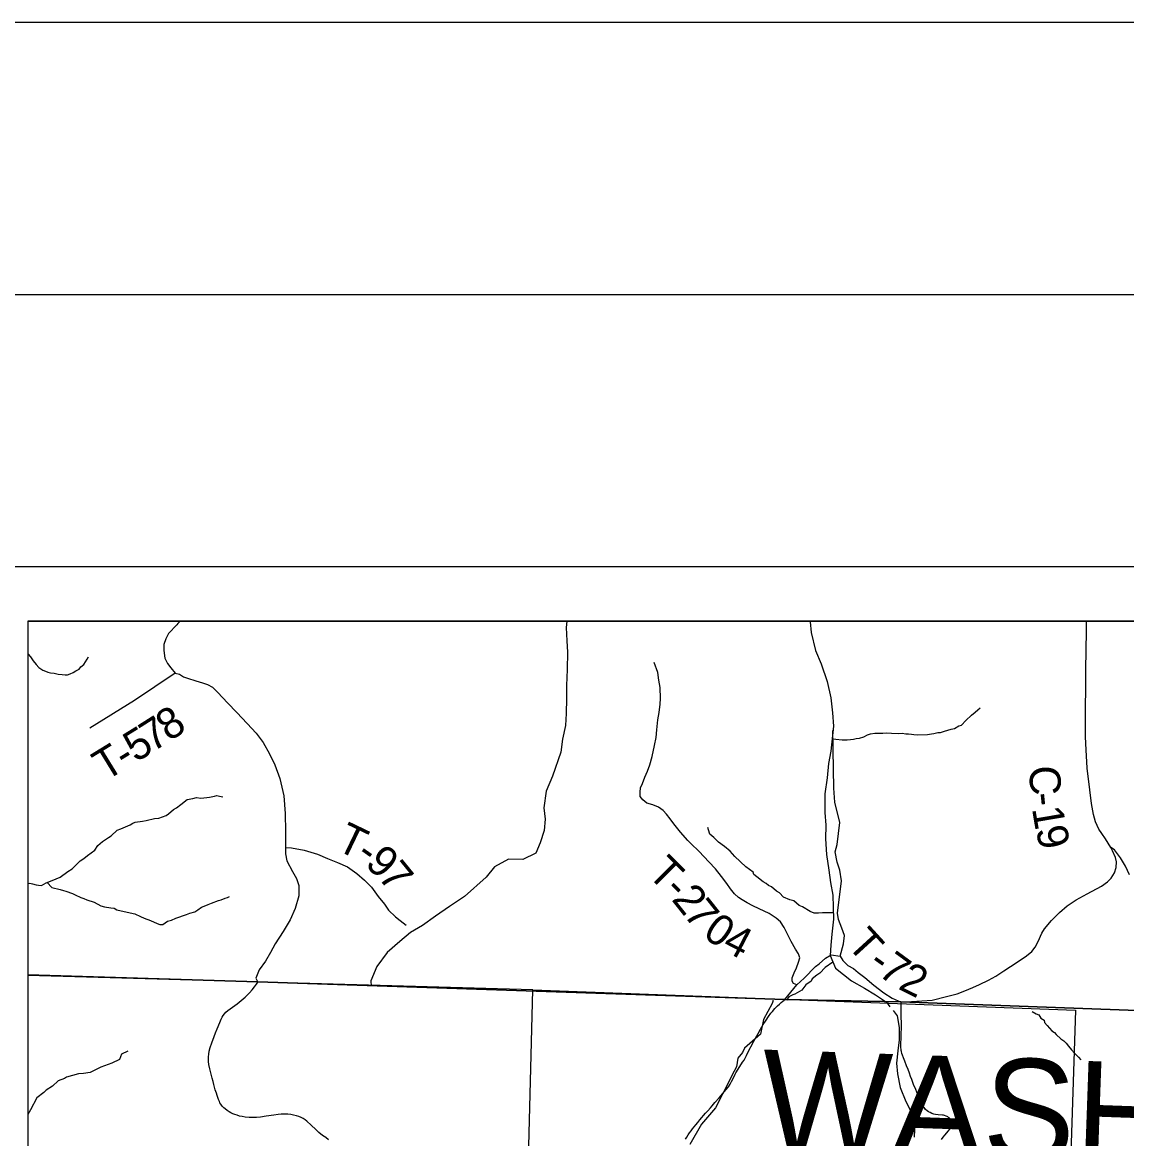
# Model space of a CAD drawing. Extents: x 6.3 to 40.3, y 9 to 31.
# Drawn here: x 8.435 to 10.464, y 28.995 to 31.046 of the extents above; entities that cross this region are included whole.
import ezdxf

# ---------------------------------------------------------------- set-up
doc = ezdxf.new("R2010")
doc.units = 0
for name, color, linetype in [('Default', 7, 'Continuous'), ('GM_X_Corporation', 7, 'Continuous'), ('GM_X_County_Road', 7, 'Continuous'), ('GM_X_County_Road_Text', 7, 'Continuous'), ('GM_X_County_Text', 7, 'Continuous'), ('GM_X_Minor_River', 7, 'Continuous'), ('GM_X_Section', 7, 'Continuous'), ('GM_X_Township_Road', 7, 'Continuous'), ('GM_X_Township_Road_Text', 7, 'Continuous'), ('SH_Border', 7, 'Continuous'), ('SH_Cut_Line', 7, 'Continuous'), ('SH_Data', 7, 'Continuous')]:
    doc.layers.add(name, color=color, linetype=linetype)

msp = doc.modelspace()

# ---------------------------------------------------------------- linework, layer by layer
at = {"layer": 'Default'}
for points in [[(13.1323, 29.9457), (8.4446, 29.9457), (8.4446, 27.9161), (8.9627, 27.9002), (9.9314, 27.8681), (10.145, 27.8635), (10.7129, 27.8423), (11.7175, 27.8106), (12.5872, 27.7766), (13.0625, 27.76), (13.0974, 28.6191), (13.1136, 29.1637), (13.1156, 29.231), (13.116, 29.2473), (13.13, 29.8856)], [(12.9998, 29.9457), (8.4446, 29.9457), (8.4446, 29.2958), (8.8673, 29.2829), (9.8361, 29.2507), (10.0496, 29.2462), (10.6176, 29.225), (11.6221, 29.1933), (12.4918, 29.1593), (12.9672, 29.1426)]]:
    msp.add_lwpolyline(points, close=True, dxfattribs=at)
msp.add_lwpolyline([(12.9672, 29.1426), (12.4918, 29.1593), (11.6221, 29.1933), (10.6176, 29.225), (10.0496, 29.2462), (9.8361, 29.2507), (8.8673, 29.2829), (8.4446, 29.2958), (8.4446, 23.1457)], dxfattribs=at)
at = {"layer": 'GM_X_Corporation'}
msp.add_lwpolyline([(8.4446, 29.2945), (8.4446, 28.2864), (9.3471, 28.2622), (9.3732, 29.268)], close=True, dxfattribs=at)
at = {"layer": 'GM_X_County_Road'}
for points in [[(10.4353, 29.5296), (10.4256, 29.5455), (10.4186, 29.5552), (10.4134, 29.5635), (10.4074, 29.5766), (10.4033, 29.5901), (10.3997, 29.6106), (10.3965, 29.6359), (10.392, 29.6757), (10.3897, 29.7091), (10.3888, 29.7332), (10.3888, 29.7526), (10.3891, 29.856), (10.3906, 29.9279), (10.3908, 29.9457)], [(10.0498, 29.2457), (10.1069, 29.2492), (10.1335, 29.2558), (10.1526, 29.2608), (10.1667, 29.2666), (10.1816, 29.2724), (10.194, 29.2782), (10.2106, 29.2857), (10.2239, 29.2932), (10.2389, 29.3031), (10.2629, 29.3189), (10.2804, 29.3305), (10.2903, 29.3388), (10.2961, 29.3463), (10.3019, 29.3571), (10.3086, 29.372), (10.3135, 29.3803), (10.326, 29.3953), (10.3409, 29.4102), (10.3553, 29.4227), (10.3713, 29.4333), (10.3915, 29.4448), (10.4181, 29.4588), (10.4294, 29.4664), (10.4362, 29.4736), (10.4418, 29.4829), (10.4452, 29.493), (10.4456, 29.5031), (10.4436, 29.5115), (10.4386, 29.5236), (10.4353, 29.5296)], [(10.124, 28.9929), (10.127, 28.9975), (10.1301, 29.0013), (10.1338, 29.0054), (10.1364, 29.0082), (10.1396, 29.012), (10.1405, 29.0132), (10.1412, 29.0143), (10.1417, 29.0154), (10.1421, 29.0164), (10.1424, 29.0177), (10.1425, 29.0189), (10.1427, 29.0206), (10.1426, 29.0227), (10.1425, 29.0241), (10.1423, 29.0254), (10.1419, 29.0269), (10.1413, 29.0285), (10.1407, 29.0298), (10.1397, 29.0312), (10.1387, 29.0325), (10.1379, 29.0332), (10.137, 29.0339), (10.1358, 29.0347), (10.1344, 29.0355), (10.1327, 29.0363), (10.1297, 29.0374), (10.1278, 29.0379), (10.1259, 29.0381), (10.1178, 29.0388), (10.113, 29.0393), (10.1097, 29.0399), (10.1062, 29.041), (10.103, 29.0425), (10.1004, 29.044), (10.0975, 29.0461), (10.0948, 29.0486), (10.092, 29.0518), (10.0907, 29.0535), (10.0896, 29.0552), (10.0874, 29.0589), (10.0843, 29.0656), (10.0785, 29.0802), (10.0766, 29.0852), (10.0729, 29.0944), (10.0696, 29.1033), (10.0674, 29.1088), (10.065, 29.1152), (10.0626, 29.1215), (10.0597, 29.1288), (10.0565, 29.137), (10.0541, 29.1434), (10.0523, 29.148), (10.0513, 29.1513), (10.0504, 29.1547), (10.05, 29.1567), (10.0498, 29.1585), (10.0494, 29.1621), (10.0494, 29.1654), (10.0493, 29.1696), (10.0498, 29.1794), (10.0502, 29.1881), (10.0504, 29.1975), (10.0505, 29.2057), (10.0502, 29.2198), (10.0501, 29.2277), (10.0501, 29.2305)], [(10.0501, 29.2305), (10.05, 29.2353), (10.0498, 29.2457)]]:
    msp.add_lwpolyline(points, dxfattribs=at)
at = {"layer": 'GM_X_Minor_River'}
for points in [[(9.4355, 29.9457), (9.434, 29.9337), (9.4352, 29.9092), (9.4367, 29.8888), (9.4359, 29.8567), (9.4348, 29.8273), (9.4348, 29.8035), (9.434, 29.7759), (9.4329, 29.7541), (9.4272, 29.7288), (9.4242, 29.7046), (9.4094, 29.6608), (9.3977, 29.6333), (9.3931, 29.6023), (9.3954, 29.5819), (9.3939, 29.5608), (9.3867, 29.5385), (9.3784, 29.5193), (9.3549, 29.5076), (9.328, 29.5083), (9.3026, 29.4944), (9.2875, 29.4751), (9.2474, 29.4396), (9.2201, 29.4215), (9.194, 29.4034), (9.1705, 29.3864), (9.1482, 29.3736), (9.1285, 29.3569), (9.105, 29.3369), (9.0861, 29.3113), (9.0755, 29.2845), (9.0758, 29.2747)], [(9.8823, 29.9457), (9.8826, 29.9443), (9.8845, 29.9247), (9.8928, 29.8914), (9.9027, 29.8669), (9.914, 29.8344), (9.9208, 29.8046)], [(8.4446, 29.8861), (8.4457, 29.8847), (8.4496, 29.8802), (8.4547, 29.8724), (8.4602, 29.8656), (8.4648, 29.8604), (8.4725, 29.8553), (8.4771, 29.8535), (8.4817, 29.8521), (8.4867, 29.8507), (8.4931, 29.8497), (8.5004, 29.8483), (8.508, 29.8473), (8.5137, 29.8471), (8.5179, 29.8472), (8.5224, 29.8488), (8.528, 29.8512), (8.5333, 29.8544), (8.5389, 29.8572), (8.5422, 29.8614), (8.5478, 29.8661), (8.5511, 29.8707), (8.5537, 29.8757), (8.5562, 29.88)], [(9.9208, 29.8046), (9.9239, 29.7771), (9.9258, 29.7525), (9.9205, 29.7065), (9.9163, 29.6838), (9.914, 29.6574), (9.9095, 29.628), (9.9095, 29.594), (9.9114, 29.571), (9.911, 29.5457), (9.9129, 29.517), (9.9167, 29.4879), (9.9201, 29.4656), (9.9242, 29.4422), (9.9257, 29.3977), (9.9227, 29.3705), (9.9204, 29.3505), (9.9193, 29.3312), (9.9291, 29.3082), (9.9586, 29.2848), (9.9825, 29.2712), (10.0026, 29.2588), (10.023, 29.2452), (10.0293, 29.2371)], [(9.9231, 29.7293), (9.9254, 29.7291), (9.9296, 29.7284), (9.9417, 29.7272), (9.9505, 29.7274), (9.9569, 29.7279), (9.9622, 29.7284), (9.9675, 29.7297), (9.9732, 29.7306), (9.9814, 29.733), (9.9878, 29.7366), (9.9935, 29.7382), (10.0018, 29.7396), (10.0162, 29.7399), (10.0223, 29.7404), (10.0321, 29.7399), (10.0454, 29.739), (10.0515, 29.7395), (10.0587, 29.7386), (10.0633, 29.7383), (10.069, 29.7376), (10.0732, 29.737), (10.0804, 29.7368), (10.0982, 29.7372), (10.1054, 29.7388), (10.11, 29.7393), (10.1171, 29.741), (10.1224, 29.7411), (10.1296, 29.7432), (10.142, 29.7469), (10.1477, 29.7485), (10.156, 29.7529), (10.1609, 29.7545), (10.1686, 29.7631), (10.179, 29.7728), (10.1861, 29.7783), (10.1906, 29.7825), (10.1954, 29.7865)], [(8.4446, 29.4634), (8.4485, 29.4642), (8.4535, 29.4631), (8.4603, 29.461), (8.4645, 29.4604), (8.4702, 29.4601), (8.4785, 29.4648), (8.4837, 29.4665), (8.4969, 29.4721), (8.504, 29.4753), (8.5186, 29.4855), (8.5261, 29.4902), (8.541, 29.5054), (8.5477, 29.5093), (8.5544, 29.5148), (8.5678, 29.525), (8.5737, 29.5331), (8.5823, 29.5405), (8.5928, 29.5483), (8.598, 29.5511), (8.6092, 29.5616), (8.6156, 29.5641), (8.6332, 29.5713), (8.6377, 29.5744), (8.6422, 29.5761), (8.6555, 29.5779), (8.6623, 29.5792), (8.6778, 29.5829), (8.6853, 29.5835), (8.6989, 29.5887), (8.7034, 29.5915), (8.7127, 29.5997), (8.7179, 29.6025), (8.7262, 29.6087), (8.7377, 29.6177), (8.7479, 29.6198), (8.7551, 29.6215), (8.7627, 29.6206), (8.7741, 29.6216), (8.7786, 29.6221), (8.788, 29.6242), (8.7922, 29.625), (8.7972, 29.624), (8.8033, 29.623)], [(9.9253, 29.4096), (9.9153, 29.4097), (9.9054, 29.4099), (9.8979, 29.4089), (9.8903, 29.4088), (9.883, 29.412), (9.8688, 29.4208), (9.8626, 29.4234), (9.8526, 29.4315), (9.8453, 29.4336), (9.8338, 29.4383), (9.8261, 29.4465), (9.8211, 29.4494), (9.8114, 29.4572), (9.8064, 29.4597), (9.8018, 29.4638), (9.7964, 29.4667), (9.7848, 29.4756), (9.7794, 29.48), (9.7778, 29.4845), (9.7643, 29.4941), (9.7445, 29.513), (9.7356, 29.5227), (9.7252, 29.5316), (9.714, 29.5397), (9.7054, 29.5483), (9.6985, 29.5542), (9.6957, 29.5621), (9.6944, 29.5662)], [(8.4804, 29.4654), (8.4889, 29.4563), (8.5042, 29.4525), (8.5103, 29.4507), (8.5145, 29.4497), (8.5267, 29.445), (8.5317, 29.4429), (8.5421, 29.4378), (8.5478, 29.436), (8.5532, 29.4335), (8.5669, 29.4292), (8.5792, 29.4227), (8.5857, 29.4209), (8.5971, 29.4189), (8.6036, 29.4179), (8.6086, 29.4153), (8.633, 29.4094), (8.6414, 29.4077), (8.6521, 29.403), (8.6586, 29.3997), (8.6705, 29.3958), (8.6824, 29.39), (8.6877, 29.3882), (8.6927, 29.3883), (8.7016, 29.3943), (8.7088, 29.3963), (8.7167, 29.3999), (8.7363, 29.4064), (8.7427, 29.4089), (8.7517, 29.4117), (8.7574, 29.4149), (8.7641, 29.42), (8.769, 29.4216), (8.7761, 29.4248), (8.7821, 29.4272), (8.7953, 29.4325), (8.8002, 29.4337), (8.8074, 29.4365), (8.8115, 29.4378), (8.8156, 29.4394)], [(9.9244, 29.3192), (9.9103, 29.3093), (9.9003, 29.2988), (9.895, 29.2953), (9.8861, 29.2882), (9.8843, 29.284), (9.8749, 29.2773), (9.8676, 29.2677), (9.8548, 29.2602), (9.8507, 29.2589), (9.8436, 29.2553), (9.8391, 29.2492)], [(9.8148, 29.247), (9.8149, 29.2488), (9.8131, 29.243), (9.7967, 29.2136), (9.7913, 29.187), (9.7623, 29.1612), (9.7586, 29.1532), (9.75, 29.1428), (9.7475, 29.1265), (9.7396, 29.1123), (9.7341, 29.1001), (9.7088, 29.0512), (9.6829, 29.0213), (9.6616, 28.9839)], [(10.035, 29.2299), (10.0423, 29.2206), (10.0461, 29.1987), (10.0465, 29.1764), (10.0438, 29.1561), (10.0415, 29.1334), (10.0434, 29.1141), (10.0483, 29.0885), (10.0586, 29.0632), (10.0714, 29.0379), (10.0744, 29.0118), (10.0737, 28.9975)], [(10.291, 29.2285), (10.2982, 29.2239), (10.3027, 29.222), (10.3066, 29.2164), (10.3127, 29.2122), (10.3135, 29.2081), (10.3185, 29.2028), (10.327, 29.193), (10.3316, 29.19), (10.335, 29.1859), (10.3431, 29.1784), (10.3492, 29.1743), (10.3534, 29.1701), (10.3576, 29.1645), (10.363, 29.1581), (10.3688, 29.1517), (10.3757, 29.1442), (10.3799, 29.1396)], [(8.6289, 29.1556), (8.6168, 29.1498), (8.6135, 29.1402), (8.5995, 29.1336), (8.5791, 29.1262), (8.5681, 29.1204), (8.5594, 29.1165), (8.5469, 29.1145), (8.5382, 29.1136), (8.5268, 29.1105), (8.5162, 29.1077), (8.5121, 29.1054), (8.5004, 29.1007), (8.4902, 29.0914), (8.4785, 29.0841), (8.474, 29.0795), (8.4612, 29.0695), (8.45, 29.0477), (8.4446, 29.0394)]]:
    msp.add_lwpolyline(points, dxfattribs=at)
at = {"layer": 'GM_X_Section'}
msp.add_lwpolyline([(9.3732, 29.268), (10.3703, 29.2306), (10.3378, 28.2352), (9.3471, 28.2622)], close=True, dxfattribs=at)
at = {"layer": 'GM_X_Township_Road'}
msp.add_line((8.7251, 29.9457), (8.7207, 29.9411), dxfattribs=at)
for points in [[(8.7207, 29.9411), (8.7185, 29.9388), (8.7036, 29.923), (8.6986, 29.913), (8.6946, 29.9029), (8.6946, 29.8919), (8.6966, 29.8778), (8.7016, 29.8678), (8.7076, 29.8598), (8.7156, 29.8497), (8.7234, 29.8482), (8.7308, 29.843), (8.7381, 29.8408), (8.7539, 29.8356), (8.7656, 29.8324), (8.775, 29.8293), (8.7845, 29.824), (8.794, 29.8145), (8.812, 29.7955), (8.8289, 29.7775), (8.8478, 29.7575), (8.8647, 29.7396), (8.8774, 29.7227), (8.889, 29.7016), (8.8985, 29.6816), (8.908, 29.6562), (8.9153, 29.6246), (8.9175, 29.5919), (8.9185, 29.5592), (8.9185, 29.5296), (8.9185, 29.518), (8.9206, 29.5054), (8.9312, 29.4853), (8.9386, 29.4727), (8.9428, 29.46), (8.9428, 29.441), (8.9364, 29.4178), (8.9269, 29.3967), (8.9143, 29.3756), (8.8995, 29.3524), (8.8911, 29.3366), (8.8816, 29.3207), (8.87, 29.3049), (8.8638, 29.2898), (8.8675, 29.2823)], [(9.6745, 29.5265), (9.6675, 29.5325), (9.658, 29.5426), (9.6443, 29.5581), (9.6324, 29.5733), (9.6255, 29.5822), (9.6186, 29.5912), (9.6124, 29.5974), (9.604, 29.604), (9.5936, 29.6082), (9.5825, 29.6113), (9.5749, 29.6172), (9.5704, 29.6234), (9.5701, 29.6314), (9.5708, 29.6394), (9.5746, 29.6474), (9.5791, 29.6588), (9.5836, 29.6699), (9.5881, 29.6813), (9.5923, 29.6969), (9.5968, 29.717), (9.5995, 29.732), (9.6006, 29.7458), (9.6026, 29.7642), (9.6051, 29.778), (9.6068, 29.793), (9.6078, 29.8037), (9.6068, 29.8235), (9.6047, 29.837), (9.6026, 29.8512), (9.5961, 29.8696)], [(8.7156, 29.8497), (8.6411, 29.7996), (8.5586, 29.7488)], [(9.9322, 29.5352), (9.9375, 29.5756), (9.9283, 29.6132), (9.9265, 29.6384), (9.9242, 29.7444)], [(9.9349, 29.3973), (9.9331, 29.4092), (9.94, 29.4685), (9.9373, 29.4878), (9.9325, 29.503), (9.9289, 29.5215), (9.9322, 29.5352)], [(8.9185, 29.5296), (8.9296, 29.5288), (8.9526, 29.525), (8.9775, 29.5173), (8.9957, 29.5096), (9.0139, 29.502), (9.0321, 29.4943), (9.0494, 29.4818), (9.0638, 29.4694), (9.0762, 29.4569), (9.0887, 29.4396), (9.1002, 29.4253), (9.1078, 29.4147), (9.1203, 29.4023), (9.1289, 29.3955), (9.1404, 29.3869)], [(9.858, 29.2773), (9.8518, 29.2797), (9.8494, 29.2839), (9.8497, 29.2901), (9.853, 29.2991), (9.8575, 29.3086), (9.8611, 29.3187), (9.8637, 29.327), (9.8611, 29.3345), (9.856, 29.3428), (9.848, 29.3571), (9.8351, 29.3827), (9.8283, 29.3928), (9.8203, 29.4), (9.8131, 29.4045), (9.8072, 29.4083), (9.7982, 29.4128), (9.7887, 29.417), (9.7771, 29.4226), (9.7667, 29.4283), (9.7577, 29.4333), (9.7509, 29.4381), (9.7437, 29.4446), (9.7363, 29.4539), (9.7295, 29.4634), (9.7196, 29.4765), (9.7086, 29.4905), (9.6964, 29.5033), (9.6881, 29.5125), (9.6782, 29.5232), (9.6745, 29.5265)], [(10.4695, 29.4797), (10.4623, 29.4955), (10.4531, 29.5104), (10.4422, 29.5255), (10.4353, 29.5296)], [(9.9379, 29.33), (9.9441, 29.3529), (9.9456, 29.3681), (9.9411, 29.3815), (9.9349, 29.3973)], [(9.8363, 29.2502), (9.858, 29.2773), (9.8714, 29.2898), (9.8924, 29.3108), (9.8992, 29.3161), (9.9108, 29.3264), (9.9215, 29.3327), (9.9379, 29.33)], [(9.9379, 29.33), (9.9429, 29.322), (9.9522, 29.3127), (9.9623, 29.3074), (9.9712, 29.3002), (9.9831, 29.2907), (9.9995, 29.2767), (10.0182, 29.2627), (10.0337, 29.2529), (10.0498, 29.2457)], [(8.9975, 28.9928), (8.9923, 28.9966), (8.9865, 29.0007), (8.9797, 29.0061), (8.9739, 29.0115), (8.9654, 29.0196), (8.9576, 29.0267), (8.9545, 29.0292), (8.951, 29.0315), (8.9472, 29.0336), (8.943, 29.0353), (8.9385, 29.0367), (8.9334, 29.0381), (8.9284, 29.0389), (8.9225, 29.0395), (8.9163, 29.0399), (8.9106, 29.0397), (8.9051, 29.039), (8.8969, 29.0378), (8.8828, 29.0358), (8.8724, 29.0344), (8.8649, 29.0337), (8.8575, 29.0334), (8.8519, 29.0335), (8.8445, 29.0343), (8.839, 29.0352), (8.8341, 29.0362), (8.8295, 29.0376), (8.8254, 29.039), (8.8217, 29.0406), (8.8181, 29.0423), (8.8147, 29.0443), (8.8109, 29.0467), (8.8076, 29.0493), (8.8052, 29.0515), (8.8022, 29.0547), (8.7996, 29.0582), (8.798, 29.0608), (8.7968, 29.063), (8.7951, 29.0669), (8.7926, 29.074), (8.7914, 29.0781), (8.7894, 29.0846), (8.7868, 29.0942), (8.7853, 29.0996), (8.7837, 29.1056), (8.7794, 29.123), (8.7777, 29.1309), (8.7769, 29.1365), (8.7767, 29.1408), (8.7768, 29.1451), (8.7773, 29.1501), (8.7784, 29.1556), (8.7802, 29.1622), (8.7831, 29.171), (8.7874, 29.1826), (8.79, 29.189), (8.7931, 29.1965), (8.7976, 29.208), (8.8002, 29.2143), (8.8021, 29.2182), (8.8041, 29.2213), (8.8062, 29.2242), (8.809, 29.227), (8.8126, 29.2304), (8.8165, 29.2334), (8.8293, 29.2423), (8.8371, 29.2486), (8.844, 29.2548), (8.852, 29.2627), (8.8571, 29.2681), (8.8614, 29.2734), (8.8649, 29.2785), (8.8675, 29.2823)], [(9.6535, 28.9938), (9.6559, 28.9976), (9.6585, 29.0015), (9.6611, 29.0052), (9.664, 29.0092), (9.6666, 29.0127), (9.6692, 29.0164), (9.6725, 29.0204), (9.676, 29.0244), (9.6799, 29.0291), (9.6904, 29.0413), (9.6945, 29.046), (9.6994, 29.0515), (9.7023, 29.0548), (9.7076, 29.0609), (9.7153, 29.0698), (9.7282, 29.0849), (9.7325, 29.0902), (9.7357, 29.0948), (9.7384, 29.0996), (9.7435, 29.1103), (9.7451, 29.1135), (9.7463, 29.1157), (9.7474, 29.1178), (9.7586, 29.135), (9.7611, 29.1391), (9.7655, 29.1473), (9.7678, 29.1517), (9.7793, 29.1737), (9.7869, 29.1879), (9.7915, 29.196), (9.7966, 29.2045), (9.8016, 29.2124), (9.8061, 29.2191), (9.8105, 29.225), (9.8132, 29.2284), (9.818, 29.2338), (9.8226, 29.2386), (9.8261, 29.2419), (9.8294, 29.2447), (9.8327, 29.2474), (9.8351, 29.2494), (9.8363, 29.2502)]]:
    msp.add_lwpolyline(points, dxfattribs=at)
at = {"layer": 'SH_Border'}
msp.add_lwpolyline([(7.8446, 30.5457), (39.8446, 30.5457), (39.8446, 9.5457), (7.8446, 9.5457)], close=True, dxfattribs=at)
at = {"layer": 'SH_Cut_Line'}
msp.add_lwpolyline([(6.3446, 9.0457), (40.3446, 9.0457), (40.3446, 31.0457), (6.3446, 31.0457)], close=True, dxfattribs=at)
for points in [[(15.2446, 29.9457), (8.4446, 29.9457), (8.4446, 29.2958), (8.8673, 29.2829), (9.8361, 29.2507), (10.0496, 29.2462), (10.6176, 29.225), (11.6221, 29.1933), (12.4918, 29.1593), (12.9672, 29.1426)], [(12.9672, 29.1426), (12.4918, 29.1593), (11.6221, 29.1933), (10.6176, 29.225), (10.0496, 29.2462), (9.8361, 29.2507), (8.8673, 29.2829), (8.4446, 29.2958), (8.4446, 23.1457)]]:
    msp.add_lwpolyline(points, dxfattribs=at)
at = {"layer": 'SH_Data'}
for p, q in [((8.3446, 30.0457), (15.3446, 30.0457)), ((8.4446, 29.9457), (8.4446, 23.1457)), ((8.4446, 29.9457), (15.2446, 29.9457))]:
    msp.add_line(p, q, dxfattribs=at)

# ---------------------------------------------------------------- texts
at = {"layer": 'GM_X_County_Road_Text'}
for s, rotation, p in [('C', 272.1237, (10.2853, 29.6793)), ('-', 275.7938, (10.2873, 29.6287)), ('1', 279.6443, (10.2902, 29.6014)), ('9', 282.9334, (10.2968, 29.5634))]:
    msp.add_text(s, height=0.0568, rotation=rotation, dxfattribs=at).set_placement(p)
at = {"layer": 'GM_X_County_Text'}
msp.add_text('WASHINGTON COUNTY', height=0.189394, rotation=357.9773, dxfattribs=at).set_placement((9.7904, 28.9692))
at = {"layer": 'GM_X_Township_Road_Text'}
for s, rotation, p in [('8', 33.609, (8.7045, 29.7233)), ('7', 32.3352, (8.6737, 29.7039)), ('5', 31.8392, (8.6435, 29.6851)), ('T', 31.562, (8.5872, 29.6505)), ('-', 31.6238, (8.6235, 29.6727)), ('T', 334.3616, (9.009, 29.5267)), ('-', 324.8046, (9.0451, 29.5096)), ('9', 317.5653, (9.0625, 29.4975)), ('T', 314.9061, (9.5817, 29.4798)), ('7', 309.2174, (9.0866, 29.4757)), ('-', 313.6365, (9.6115, 29.4499)), ('2', 308.4672, (9.6267, 29.434)), ('7', 308.3672, (9.6484, 29.4067)), ('0', 324.9738, (9.6832, 29.3669)), ('4', 332.5524, (9.7188, 29.3426)), ('T', 312.4148, (9.9485, 29.35)), ('7', 323.8662, (10.0053, 29.2967)), ('-', 324.2793, (9.9866, 29.3101)), ('2', 333.6858, (10.0424, 29.2707))]:
    msp.add_text(s, height=0.0568, rotation=rotation, dxfattribs=at).set_placement(p)

doc.saveas('drawing.dxf')
